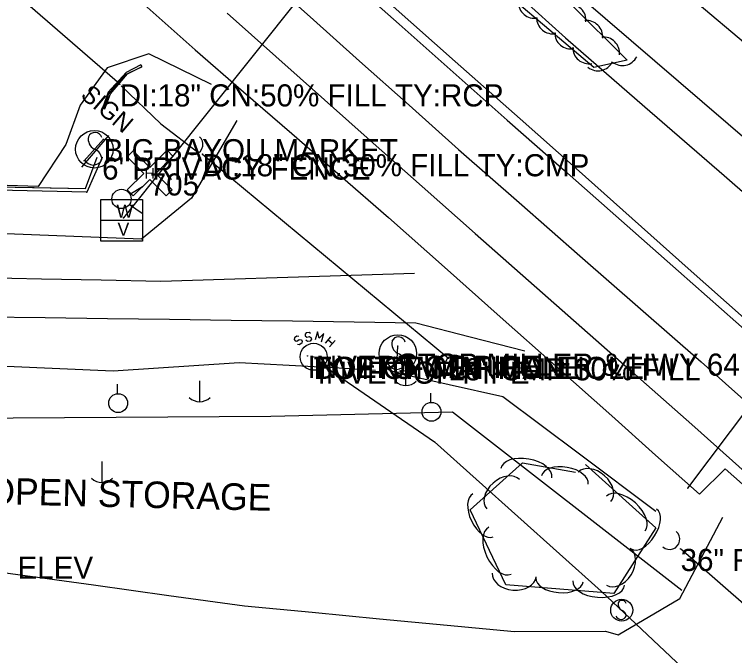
# Model space of a CAD drawing. Extents: x 1441650 to 1491889, y 345904 to 358319.
# Drawn here: x 1443649 to 1443811.8, y 356013 to 356157.9 of the extents above; entities that cross this region are included whole.
import ezdxf

# ---------------------------------------------------------------- set-up
doc = ezdxf.new("R2010")
doc.units = 0
for name, color, linetype in [('S_CROSS_DRAIN', 7, 'Continuous'), ('S_CROSS_DRAIN_ANNOT', 7, 'Continuous'), ('S_DITCHLINE', 7, 'Continuous'), ('S_DRG_PT_SYM', 7, 'Continuous'), ('S_EDGE_PAVEMENT', 7, 'Continuous'), ('S_FENCE', 7, 'Continuous'), ('S_FENCE_ANNOT', 7, 'Continuous'), ('S_GAS_UTILITIES', 7, 'Continuous'), ('S_GRAVEL_ROAD', 7, 'Continuous'), ('S_HEADWALL', 7, 'Continuous'), ('S_MANHOLE_ANNOT', 7, 'Continuous'), ('S_MISC_BOUNDARY', 7, 'Continuous'), ('S_MISC_BOUNDARY_ANNOT', 7, 'Continuous'), ('S_MSC_PT_SYM', 7, 'Continuous'), ('S_PAVEMENT_CROWN', 7, 'Continuous'), ('S_PHOTO_CTL', 7, 'Continuous'), ('S_PHOTO_CTL_ANNOT', 7, 'Continuous'), ('S_SANITARY_SEWER', 7, 'Continuous'), ('S_SANITARY_SEWER_ANNOT', 7, 'Continuous'), ('S_SECONDARY_CTL_ANNOT', 7, 'Continuous'), ('S_SHOULDER', 7, 'Continuous'), ('S_SIGN', 7, 'Continuous'), ('S_SIGN_ANNOT', 7, 'Continuous'), ('S_STREAM', 7, 'Continuous'), ('S_TREE', 7, 'Continuous'), ('S_UTILITY_POLE', 7, 'Continuous'), ('S_UTL_PT_SYM', 7, 'Continuous'), ('S_WATER_UTILITIES', 7, 'Continuous')]:
    doc.layers.add(name, color=color, linetype=linetype)

msp = doc.modelspace()

# ---------------------------------------------------------------- linework, layer by layer
at = {"layer": 'S_CROSS_DRAIN'}
for p, q in [((1443672.79, 356142.12), (1443640.48, 356170.36)), ((1443691.48, 356126.34), (1443747.11, 356080.23)), ((1443824.36, 356015.47), (1443799.56, 356037.15))]:
    msp.add_line(p, q, dxfattribs=at)
for centre, start, end in [((1443689.3, 356128.54), 229.3018, 49.631), ((1443748.54, 356078.61), 49.5453, 229.8745), ((1443797.08, 356039.32), 228.843, 49.1722)]:
    msp.add_arc(centre, 2.3, start, end, dxfattribs=at)
at = {"layer": 'S_DITCHLINE'}
for points in [[(1443680.55, 356237.92), (1443694.76, 356224.43), (1443704.6, 356215.46), (1443714.45, 356206.48), (1443724.29, 356197.51), (1443734.14, 356188.54), (1443743.98, 356179.56), (1443753.82, 356170.59), (1443763.67, 356161.61), (1443773.51, 356152.64), (1443791.44, 356137.07), (1443809.37, 356121.49), (1443827.3, 356105.92), (1443845.23, 356090.35), (1443857.24, 356080), (1443869.26, 356069.66), (1443881.27, 356059.31), (1443893.28, 356048.97), (1443905.29, 356038.62), (1443917.31, 356028.27), (1443929.32, 356017.93), (1443941.33, 356007.58), (1443955.28, 355994.97)], [(1443673.13, 356141.77), (1443682.07, 356133.2), (1443690.73, 356126.55)], [(1443735.12, 356077.01), (1443759.4, 356071.57), (1443776.69, 356058.61), (1443793.99, 356045.65)]]:
    msp.add_lwpolyline(points, dxfattribs=at)
at = {"layer": 'S_DRG_PT_SYM'}
for points in [[(1443672.79, 356142.12), (1443672.79, 356142.17), (1443672.79, 356142.12), (1443672.74, 356142.12), (1443672.79, 356142.12), (1443672.79, 356142.07), (1443672.79, 356142.12), (1443672.84, 356142.12)], [(1443691.48, 356126.34), (1443691.48, 356126.39), (1443691.48, 356126.34), (1443691.43, 356126.34), (1443691.48, 356126.34), (1443691.48, 356126.29), (1443691.48, 356126.34), (1443691.53, 356126.34)], [(1443747.11, 356080.23), (1443747.11, 356080.28), (1443747.11, 356080.23), (1443747.06, 356080.23), (1443747.11, 356080.23), (1443747.11, 356080.18), (1443747.11, 356080.23), (1443747.16, 356080.23)], [(1443799.56, 356037.15), (1443799.56, 356037.2), (1443799.56, 356037.15), (1443799.51, 356037.15), (1443799.56, 356037.15), (1443799.56, 356037.1), (1443799.56, 356037.15), (1443799.61, 356037.15)]]:
    msp.add_lwpolyline(points, dxfattribs=at)
at = {"layer": 'S_EDGE_PAVEMENT'}
for points in [[(1443723.71, 356166.59), (1443735.93, 356155.73), (1443748.15, 356144.87), (1443760.37, 356134.01), (1443773.28, 356122.63), (1443786.2, 356111.25), (1443799.12, 356099.87), (1443812.04, 356088.49), (1443823.59, 356078.32), (1443835.15, 356068.16), (1443846.7, 356058), (1443858.25, 356047.84), (1443869.39, 356037.92), (1443880.54, 356028.01), (1443891.68, 356018.09), (1443902.82, 356008.18), (1443913.29, 355999.01), (1443923.76, 355989.84), (1443934.23, 355980.67), (1443944.7, 355971.51), (1443954.35, 355962.94)], [(1443697.06, 356158.21), (1443708.07, 356148.42), (1443719.08, 356138.63), (1443730.1, 356128.85), (1443741.11, 356119.06), (1443753.15, 356108.44), (1443765.2, 356097.81), (1443777.24, 356087.19), (1443789.29, 356076.56), (1443802.07, 356065.22), (1443814.85, 356053.88), (1443827.63, 356042.53), (1443840.41, 356031.19), (1443851.59, 356021.32), (1443862.76, 356011.45), (1443873.94, 356001.58), (1443885.11, 355991.7), (1443896.1, 355982), (1443907.08, 355972.3), (1443918.07, 355962.6), (1443929.05, 355952.89), (1443947.7, 355936.5), (1443966.34, 355920.1)], [(1443693.54, 356142.08), (1443679.39, 356149.03), (1443669.96, 356145.84), (1443663.83, 356137.42), (1443660.57, 356128.49), (1443654.33, 356119.05), (1443635.57, 356119.62), (1443616.81, 356120.19), (1443592.99, 356120.68), (1443569.18, 356121.16)], [(1443699.22, 356133.91), (1443688.99, 356116.39), (1443677.69, 356107.13), (1443652.84, 356108.1), (1443628, 356109.08), (1443611.97, 356109.28), (1443595.95, 356109.49), (1443579.93, 356109.69), (1443563.9, 356109.9), (1443548.93, 356109.76), (1443533.95, 356109.62), (1443518.97, 356109.48), (1443503.99, 356109.34), (1443480.84, 356109.65), (1443457.7, 356109.96)], [(1443764.33, 356081.82), (1443752.02, 356084.99), (1443739.71, 356088.17), (1443725.78, 356088.37), (1443711.86, 356088.57), (1443697.94, 356088.77), (1443684.02, 356088.98), (1443669.99, 356089.15), (1443655.95, 356089.32), (1443641.92, 356089.49), (1443627.89, 356089.66), (1443612.24, 356089.76), (1443596.6, 356089.86), (1443580.95, 356089.96), (1443565.3, 356090.06), (1443550.16, 356090.34), (1443535.01, 356090.63), (1443519.86, 356090.91), (1443504.71, 356091.19), (1443480.34, 356091.93), (1443455.97, 356092.66)]]:
    msp.add_lwpolyline(points, dxfattribs=at)
at = {"layer": 'S_FENCE'}
for p, q in [((1443668.79, 356125.59), (1443665.32, 356117.74)), ((1443665.32, 356117.74), (1443617.44, 356118.85))]:
    msp.add_line(p, q, dxfattribs=at)
for points in [[(1443565.47, 356120.47), (1443665.06, 356118.6), (1443667.69, 356125.66)], [(1443653.45, 356118.82), (1443665.06, 356118.6), (1443667.69, 356125.66)], [(1443633.46, 356119.2), (1443653.45, 356118.82)]]:
    msp.add_lwpolyline(points, dxfattribs=at)
at = {"layer": 'S_GAS_UTILITIES'}
msp.add_line((1443801.19, 356050.9), (1443823.8, 356080.93), dxfattribs=at)
at = {"layer": 'S_GRAVEL_ROAD'}
msp.add_lwpolyline([(1443578.08, 356085.84), (1443571.05, 356073.38), (1443587.74, 356056.77), (1443598.97, 356051.01), (1443610.21, 356045.25), (1443621.44, 356039.49), (1443632.67, 356033.73), (1443649.75, 356031.36), (1443666.83, 356028.99), (1443683.91, 356026.63), (1443700.99, 356024.26), (1443716.25, 356022.82), (1443731.52, 356021.38), (1443746.78, 356019.93), (1443762.04, 356018.49), (1443782.61, 356018.58), (1443785.45, 356017.75), (1443799.38, 356025.93), (1443809.1, 356044.32)], dxfattribs=at)
at = {"layer": 'S_HEADWALL'}
msp.add_lwpolyline([(1443677.55, 356146.52), (1443674.27, 356144.79), (1443670.19, 356140.33), (1443668.86, 356136.76), (1443669.39, 356136.57), (1443670.68, 356139.97), (1443674.57, 356144.51), (1443677.84, 356146.14)], close=True, dxfattribs=at)
msp.add_lwpolyline([(1443677.7, 356146.03), (1443673.84, 356144.16), (1443670.28, 356139.97), (1443669.21, 356136.58)], dxfattribs=at)
at = {"layer": 'S_MISC_BOUNDARY'}
msp.add_lwpolyline([(1443799.85, 356027.75), (1443748.01, 356068.05), (1443706.96, 356067.06), (1443636.91, 356066.63), (1443620.5, 356067.44), (1443589.14, 356077.85), (1443584.34, 356079.16), (1443580.08, 356067.59)], dxfattribs=at)
at = {"layer": 'S_MSC_PT_SYM'}
for points in [[(1443669.15, 356129.73), (1443669.15, 356129.78), (1443669.15, 356129.73), (1443669.1, 356129.73), (1443669.15, 356129.73), (1443669.15, 356129.68), (1443669.15, 356129.73), (1443669.2, 356129.73)], [(1443668.79, 356125.59), (1443668.79, 356125.64), (1443668.79, 356125.59), (1443668.74, 356125.59), (1443668.79, 356125.59), (1443668.79, 356125.54), (1443668.79, 356125.59), (1443668.84, 356125.59)], [(1443664.73, 356124.86), (1443664.73, 356124.91), (1443664.73, 356124.86), (1443664.68, 356124.86), (1443664.73, 356124.86), (1443664.73, 356124.81), (1443664.73, 356124.86), (1443664.78, 356124.86)], [(1443665.32, 356117.74), (1443665.32, 356117.79), (1443665.32, 356117.74), (1443665.27, 356117.74), (1443665.32, 356117.74), (1443665.32, 356117.69), (1443665.32, 356117.74), (1443665.37, 356117.74)], [(1443735.61, 356082.98), (1443735.61, 356083.03), (1443735.61, 356082.98), (1443735.56, 356082.98), (1443735.61, 356082.98), (1443735.61, 356082.93), (1443735.61, 356082.98), (1443735.66, 356082.98)], [(1443735.47, 356079.98), (1443735.47, 356080.03), (1443735.47, 356079.98), (1443735.42, 356079.98), (1443735.47, 356079.98), (1443735.47, 356079.93), (1443735.47, 356079.98), (1443735.52, 356079.98)]]:
    msp.add_lwpolyline(points, dxfattribs=at)
at = {"layer": 'S_PAVEMENT_CROWN'}
for points in [[(1443704.63, 356167.37), (1443715.81, 356157.37), (1443726.99, 356147.37), (1443738.18, 356137.38), (1443749.36, 356127.38), (1443763.07, 356115.38), (1443776.78, 356103.39), (1443790.48, 356091.4), (1443804.19, 356079.4), (1443815.22, 356069.59), (1443826.25, 356059.77), (1443837.28, 356049.95), (1443848.31, 356040.13), (1443859.64, 356030.04), (1443870.96, 356019.94), (1443882.29, 356009.85), (1443893.62, 355999.75), (1443904.5, 355990.21), (1443915.39, 355980.68), (1443926.27, 355971.14), (1443937.16, 355961.6), (1443955.85, 355945)], [(1443739.41, 356099.39), (1443725.08, 356098.93), (1443710.75, 356098.48), (1443696.42, 356098.03), (1443682.1, 356097.58), (1443668.6, 356097.84), (1443655.1, 356098.1), (1443641.61, 356098.36), (1443628.11, 356098.63), (1443611.86, 356099.26), (1443595.61, 356099.9), (1443579.36, 356100.54), (1443563.11, 356101.18), (1443548.58, 356101.06), (1443534.05, 356100.94), (1443519.52, 356100.82), (1443504.98, 356100.7), (1443481.56, 356101.18), (1443458.13, 356101.66)]]:
    msp.add_lwpolyline(points, dxfattribs=at)
at = {"layer": 'S_PHOTO_CTL'}
for p, q in [((1443674.47, 356125.72), (1443675.83, 356127.08)), ((1443675.83, 356127.08), (1443679.57, 356123.34)), ((1443679.57, 356123.34), (1443683.47, 356127.24)), ((1443683.47, 356127.24), (1443684.82, 356125.88)), ((1443678.21, 356121.99), (1443674.47, 356125.72)), ((1443684.82, 356125.88), (1443680.92, 356121.99)), ((1443674.47, 356118.25), (1443678.21, 356121.99)), ((1443680.92, 356121.99), (1443684.65, 356118.25)), ((1443679.56, 356120.63), (1443675.83, 356116.9)), ((1443683.3, 356116.9), (1443679.56, 356120.63)), ((1443675.83, 356116.9), (1443674.47, 356118.25)), ((1443684.65, 356118.25), (1443683.3, 356116.9))]:
    msp.add_line(p, q, dxfattribs=at)
at = {"layer": 'S_SANITARY_SEWER'}
for p, q in [((1443773.88, 356185.41), (1443826.09, 356141.29)), ((1443712.28, 356084.85), (1443712.21, 356084.46)), ((1443712.83, 356085.24), (1443712.28, 356084.85)), ((1443713.25, 356085.16), (1443712.83, 356085.24)), ((1443719.26, 356083.61), (1443720.5, 356085.08)), ((1443712.21, 356084.46), (1443712.4, 356084.19)), ((1443712.4, 356084.19), (1443712.83, 356084.08)), ((1443712.83, 356084.08), (1443713.37, 356084.43)), ((1443713.37, 356083.26), (1443712.98, 356083.34)), ((1443713.37, 356084.43), (1443713.83, 356084.35)), ((1443713.91, 356083.65), (1443713.37, 356083.26)), ((1443713.83, 356084.35), (1443713.99, 356084.08)), ((1443713.99, 356084.08), (1443713.91, 356083.65)), ((1443719.92, 356084.39), (1443720.89, 356083.57)), ((1443721.47, 356084.27), (1443720.23, 356082.8)), ((1443718.18, 356079.05), (1443743.95, 356061.35)), ((1443743.95, 356061.35), (1443781.62, 356027.57)), ((1443781.62, 356027.57), (1443955.36, 355864.1))]:
    msp.add_line(p, q, dxfattribs=at)
for points in [[(1443718.37, 356083.92), (1443718.91, 356085.78), (1443717.86, 356084.77), (1443717.48, 356086.21), (1443716.93, 356084.35)], [(1443715.93, 356085.78), (1443715.58, 356086.05), (1443714.92, 356085.98), (1443714.69, 356085.63), (1443714.72, 356085.32), (1443715.07, 356085.01), (1443715.69, 356085.12), (1443716.08, 356084.81), (1443716.12, 356084.5), (1443715.85, 356084.12), (1443715.23, 356084.04), (1443714.88, 356084.31)]]:
    msp.add_lwpolyline(points, dxfattribs=at)
msp.add_circle((1443716.61, 356080.55), 3.05, dxfattribs=at)
at = {"layer": 'S_SHOULDER'}
for points in [[(1443677.61, 356160.75), (1443689.85, 356149.95), (1443700.77, 356140.46), (1443711.69, 356130.98), (1443722.62, 356121.49), (1443733.54, 356112.01), (1443746.16, 356100.81), (1443758.77, 356089.6), (1443771.39, 356078.4), (1443784, 356067.2), (1443793.92, 356058.34), (1443803.84, 356049.48), (1443809.67, 356055.22), (1443824.67, 356041.91)], [(1443733.91, 356160.29), (1443748.61, 356147.31), (1443763.31, 356134.34), (1443775.96, 356123.07), (1443788.61, 356111.8), (1443801.26, 356100.53), (1443813.91, 356089.26), (1443824.55, 356079.92), (1443835.18, 356070.57), (1443845.82, 356061.23), (1443856.45, 356051.88), (1443868.59, 356041.06), (1443880.73, 356030.24), (1443892.87, 356019.43), (1443905, 356008.61), (1443915.27, 355999.79), (1443925.53, 355990.98), (1443935.79, 355982.17), (1443946.06, 355973.35), (1443955.64, 355964.67)]]:
    msp.add_lwpolyline(points, dxfattribs=at)
at = {"layer": 'S_SIGN'}
for p, q in [((1443669.15, 356129.73), (1443664.73, 356124.86)), ((1443735.47, 356079.98), (1443735.61, 356082.98))]:
    msp.add_line(p, q, dxfattribs=at)
for centre, radius in [((1443667.05, 356127.45), 4.24), ((1443735.65, 356081.28), 4.24), ((1443786.25, 356023.3), 2.49)]:
    msp.add_circle(centre, radius, dxfattribs=at)
for centre, radius, start, end in [((1443668.22, 356129.71), 2.55, 167.1196, 241.9813), ((1443667.18, 356129.61), 1.62, 16.5258, 156.8957), ((1443666.35, 356125.17), 2.38, 358.6529, 73.7063), ((1443666.79, 356126.06), 2.17, 204.641, 335.359), ((1443735.78, 356083.43), 1.62, 16.5258, 156.8957), ((1443736.82, 356083.53), 2.55, 167.1196, 241.9813), ((1443734.95, 356079), 2.38, 358.6529, 73.7063), ((1443735.39, 356079.88), 2.17, 204.641, 335.359), ((1443786.93, 356024.62), 1.5, 167.1196, 241.9813), ((1443786.32, 356024.57), 0.95, 16.5258, 156.8957), ((1443785.84, 356021.96), 1.4, 358.6529, 73.7063), ((1443786.1, 356022.47), 1.28, 204.641, 335.359)]:
    msp.add_arc(centre, radius, start, end, dxfattribs=at)
at = {"layer": 'S_SIGN_ANNOT'}
msp.add_line((1443670.21, 356130.53), (1443664.16, 356123.4), dxfattribs=at)
at = {"layer": 'S_STREAM'}
msp.add_lwpolyline([(1443730.58, 356077.44), (1443722.38, 356078.02), (1443699.77, 356079.2), (1443671.32, 356077.29), (1443621.3, 356079.47), (1443582.83, 356083.34)], dxfattribs=at)
at = {"layer": 'S_TREE'}
for points in [[(1443729.2, 356198.89), (1443774.56, 356160.39), (1443787.46, 356147.55), (1443779.94, 356145.89), (1443722.84, 356194.21), (1443693.91, 356221.89), (1443681.38, 356233.36), (1443681.99, 356240.06), (1443697.11, 356227.22), (1443730.07, 356198.29)], [(1443778.03, 356056.22), (1443793.94, 356041.88), (1443784.43, 356027.03), (1443760.04, 356029), (1443751.96, 356045.97), (1443763.79, 356056.58), (1443775.79, 356054.45)]]:
    msp.add_lwpolyline(points, dxfattribs=at)
for centre, major_axis, ratio, start_param, end_param in [((1443766.52, 356160.69), (3.27, 1.62), 0.999934, 2.664133, 4.437334), ((1443774.53, 356156.56), (-2.91, -2.19), 0.999598, 2.399337, 4.172538), ((1443770.67, 356157.17), (3.27, 1.62), 0.999934, 2.664133, 4.437334), ((1443778.32, 356152.89), (-2.91, -2.19), 0.999598, 2.399337, 4.172538), ((1443774.75, 356153.77), (3.27, 1.62), 0.999934, 2.664133, 4.437334), ((1443782.11, 356149.17), (-2.91, -2.19), 0.999598, 2.399337, 4.172538), ((1443778.82, 356150.42), (3.27, 1.62), 0.999934, 2.664133, 4.437334), ((1443786.41, 356150.01), (3.56, 0.78), 0.999971, 3.825789, 5.598989), ((1443780.89, 356148.82), (3.56, 0.78), 0.999971, 3.825789, 5.598989), ((1443764.68, 356054.27), (-5.78, 1.03), 0.55008, 3.141593, 6.283185), ((1443773.41, 356052.72), (-5.26, 0.94), 0.540699, 3.141593, 6.283185), ((1443780.11, 356051.14), (-3.68, 3.32), 0.685311, 3.141593, 6.283185), ((1443759.44, 356049.48), (-3.69, -3.31), 0.685311, 3.141593, 6.283185), ((1443787.17, 356045.13), (-4.36, 3.93), 0.55008, 3.141593, 6.283185), ((1443754.9, 356044.73), (2.3, -4.83), 0.540699, 3.141593, 6.283185), ((1443791.26, 356041.63), (2.88, 4.5), 0.540699, 3.141593, 6.283185), ((1443758.71, 356036.72), (2.52, -5.3), 0.55008, 3.141593, 6.283185), ((1443785.49, 356033.1), (2.67, 4.17), 0.685311, 3.141593, 6.283185), ((1443761.94, 356031.24), (4.94, -0.4), 0.685311, 3.141593, 6.283185), ((1443772.19, 356030.15), (5.33, -0.43), 0.540699, 3.141593, 6.283185), ((1443781.03, 356029.43), (5.85, -0.47), 0.55008, 3.141593, 6.283185)]:
    msp.add_ellipse(centre, major_axis=major_axis, ratio=ratio, start_param=start_param, end_param=end_param, dxfattribs=at)
at = {"layer": 'S_UTILITY_POLE'}
for p, q in [((1443737.39, 356078.78), (1443737.39, 356074.06)), ((1443690.79, 356075.12), (1443690.79, 356070.39)), ((1443672.3, 356072.23), (1443672.3, 356074.34)), ((1443743.11, 356070.27), (1443743.11, 356072.37)), ((1443668.72, 356056.88), (1443668.72, 356052.16))]:
    msp.add_line(p, q, dxfattribs=at)
for centre in [(1443672.42, 356070.09), (1443743.24, 356068.13)]:
    msp.add_circle(centre, 2.13, dxfattribs=at)
for centre in [(1443737.45, 356077.48), (1443690.85, 356073.82), (1443668.78, 356055.58)]:
    msp.add_arc(centre, 3.41, 226.3972, 313.6028, dxfattribs=at)
at = {"layer": 'S_UTL_PT_SYM'}
for points in [[(1443673.63, 356111.94), (1443673.63, 356111.99), (1443673.63, 356111.94), (1443673.58, 356111.94), (1443673.63, 356111.94), (1443673.63, 356111.89), (1443673.63, 356111.94), (1443673.68, 356111.94)], [(1443715.26, 356080.78), (1443715.26, 356080.83), (1443715.26, 356080.78), (1443715.21, 356080.78), (1443715.26, 356080.78), (1443715.26, 356080.73), (1443715.26, 356080.78), (1443715.31, 356080.78)], [(1443716.61, 356080.55), (1443716.61, 356080.6), (1443716.61, 356080.55), (1443716.56, 356080.55), (1443716.61, 356080.55), (1443716.61, 356080.5), (1443716.61, 356080.55), (1443716.66, 356080.55)], [(1443717.5, 356079.47), (1443717.5, 356079.52), (1443717.5, 356079.47), (1443717.45, 356079.47), (1443717.5, 356079.47), (1443717.5, 356079.42), (1443717.5, 356079.47), (1443717.55, 356079.47)], [(1443718.18, 356079.05), (1443718.18, 356079.1), (1443718.18, 356079.05), (1443718.13, 356079.05), (1443718.18, 356079.05), (1443718.18, 356079), (1443718.18, 356079.05), (1443718.23, 356079.05)], [(1443743.95, 356061.35), (1443743.95, 356061.4), (1443743.95, 356061.35), (1443743.9, 356061.35), (1443743.95, 356061.35), (1443743.95, 356061.3), (1443743.95, 356061.35), (1443744, 356061.35)], [(1443801.19, 356050.9), (1443801.19, 356050.95), (1443801.19, 356050.9), (1443801.14, 356050.9), (1443801.19, 356050.9), (1443801.19, 356050.85), (1443801.19, 356050.9), (1443801.24, 356050.9)], [(1443781.62, 356027.57), (1443781.62, 356027.62), (1443781.62, 356027.57), (1443781.57, 356027.57), (1443781.62, 356027.57), (1443781.62, 356027.52), (1443781.62, 356027.57), (1443781.67, 356027.57)]]:
    msp.add_lwpolyline(points, dxfattribs=at)
at = {"layer": 'S_WATER_UTILITIES'}
for p, q in [((1443739.55, 356194.15), (1443830.87, 356115.5)), ((1443726.64, 356178.37), (1443673.63, 356111.94)), ((1443675.08, 356117.28), (1443677.91, 356119.01)), ((1443668.5, 356116.11), (1443677.91, 356116.11)), ((1443668.5, 356106.7), (1443668.5, 356116.11)), ((1443677.91, 356116.11), (1443677.91, 356106.7)), ((1443674.96, 356114.97), (1443677.87, 356113.04)), ((1443668.5, 356111.43), (1443677.91, 356111.43)), ((1443677.91, 356106.7), (1443668.5, 356106.7))]:
    msp.add_line(p, q, dxfattribs=at)
msp.add_circle((1443673.18, 356116.22), 2.18, dxfattribs=at)

# ---------------------------------------------------------------- texts
at = {"layer": 'S_CROSS_DRAIN_ANNOT'}
for s, p in [('DI:18" CN:50% FILL TY:RCP', (1443672.79, 356137.12)), ('DI:18" CN:30% FILL TY:CMP', (1443691.48, 356121.34)), ('18" CMP 30% FILL', (1443747.11, 356075.23)), ('36" RCP 50% FILL', (1443799.56, 356032.15))]:
    msp.add_text(s, height=5, dxfattribs=at).set_placement(p)
at = {"layer": 'S_FENCE_ANNOT'}
msp.add_text("6' PRIVACY FENCE", height=5, dxfattribs=at).set_placement((1443668.79, 356120.59))
at = {"layer": 'S_MANHOLE_ANNOT'}
for s in ['TOP OF MANHOLE', 'BOTTOM OF MANHOLE']:
    msp.add_text(s, height=5, dxfattribs=at).set_placement((1443716.61, 356075.55))
at = {"layer": 'S_MISC_BOUNDARY_ANNOT'}
msp.add_text('OPEN STORAGE', height=6.0004, rotation=358.626, dxfattribs=at).set_placement((1443642.8, 356047.29))
at = {"layer": 'S_PHOTO_CTL'}
msp.add_text('H', height=2.4, rotation=360, dxfattribs=at).set_placement((1443678.39, 356120.79))
at = {"layer": 'S_PHOTO_CTL_ANNOT'}
msp.add_text('705', height=5, dxfattribs=at).set_placement((1443679.56, 356116.99))
at = {"layer": 'S_SANITARY_SEWER_ANNOT'}
for s, p in [('INVERT OF PIPE', (1443715.26, 356075.78)), ('INVET OF PIPE', (1443717.5, 356074.47))]:
    msp.add_text(s, height=5, dxfattribs=at).set_placement(p)
at = {"layer": 'S_SECONDARY_CTL_ANNOT'}
msp.add_text('PD:SET 8" NAIL 1105 TRIG ELEV', height=5, dxfattribs=at).set_placement((1443564.44, 356030.42))
at = {"layer": 'S_SIGN_ANNOT'}
msp.add_text('SIGN', height=4, rotation=319.6773, dxfattribs=at).set_placement((1443663.7, 356139.3))
for s, p in [('BIG BAYOU MARKET', (1443669.15, 356124.73)), ('STOP MILLER & HWY 64 E', (1443735.65, 356076.28))]:
    msp.add_text(s, height=5, dxfattribs=at).set_placement(p)
at = {"layer": 'S_WATER_UTILITIES'}
for s, p in [('W', (1443672.05, 356111.96)), ('V', (1443672.28, 356107.89))]:
    msp.add_text(s, height=3, rotation=360, dxfattribs=at).set_placement(p)

doc.saveas('drawing.dxf')
